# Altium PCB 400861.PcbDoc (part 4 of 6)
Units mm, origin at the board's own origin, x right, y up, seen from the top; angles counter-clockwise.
Board outline 145 x 63.5 mm, 8 copper layers (Top Side, Mid-Layer 1, Mid-Layer 2, Mid-Layer 3, Mid-Layer 4, Mid-Layer 5, Mid-Layer 6, Bottom Side), stack 1.529 mm thick; 284 components, 233 nets, 1158 pads, 3522 vias.
Unrouted connection lines stored in the file: 1.
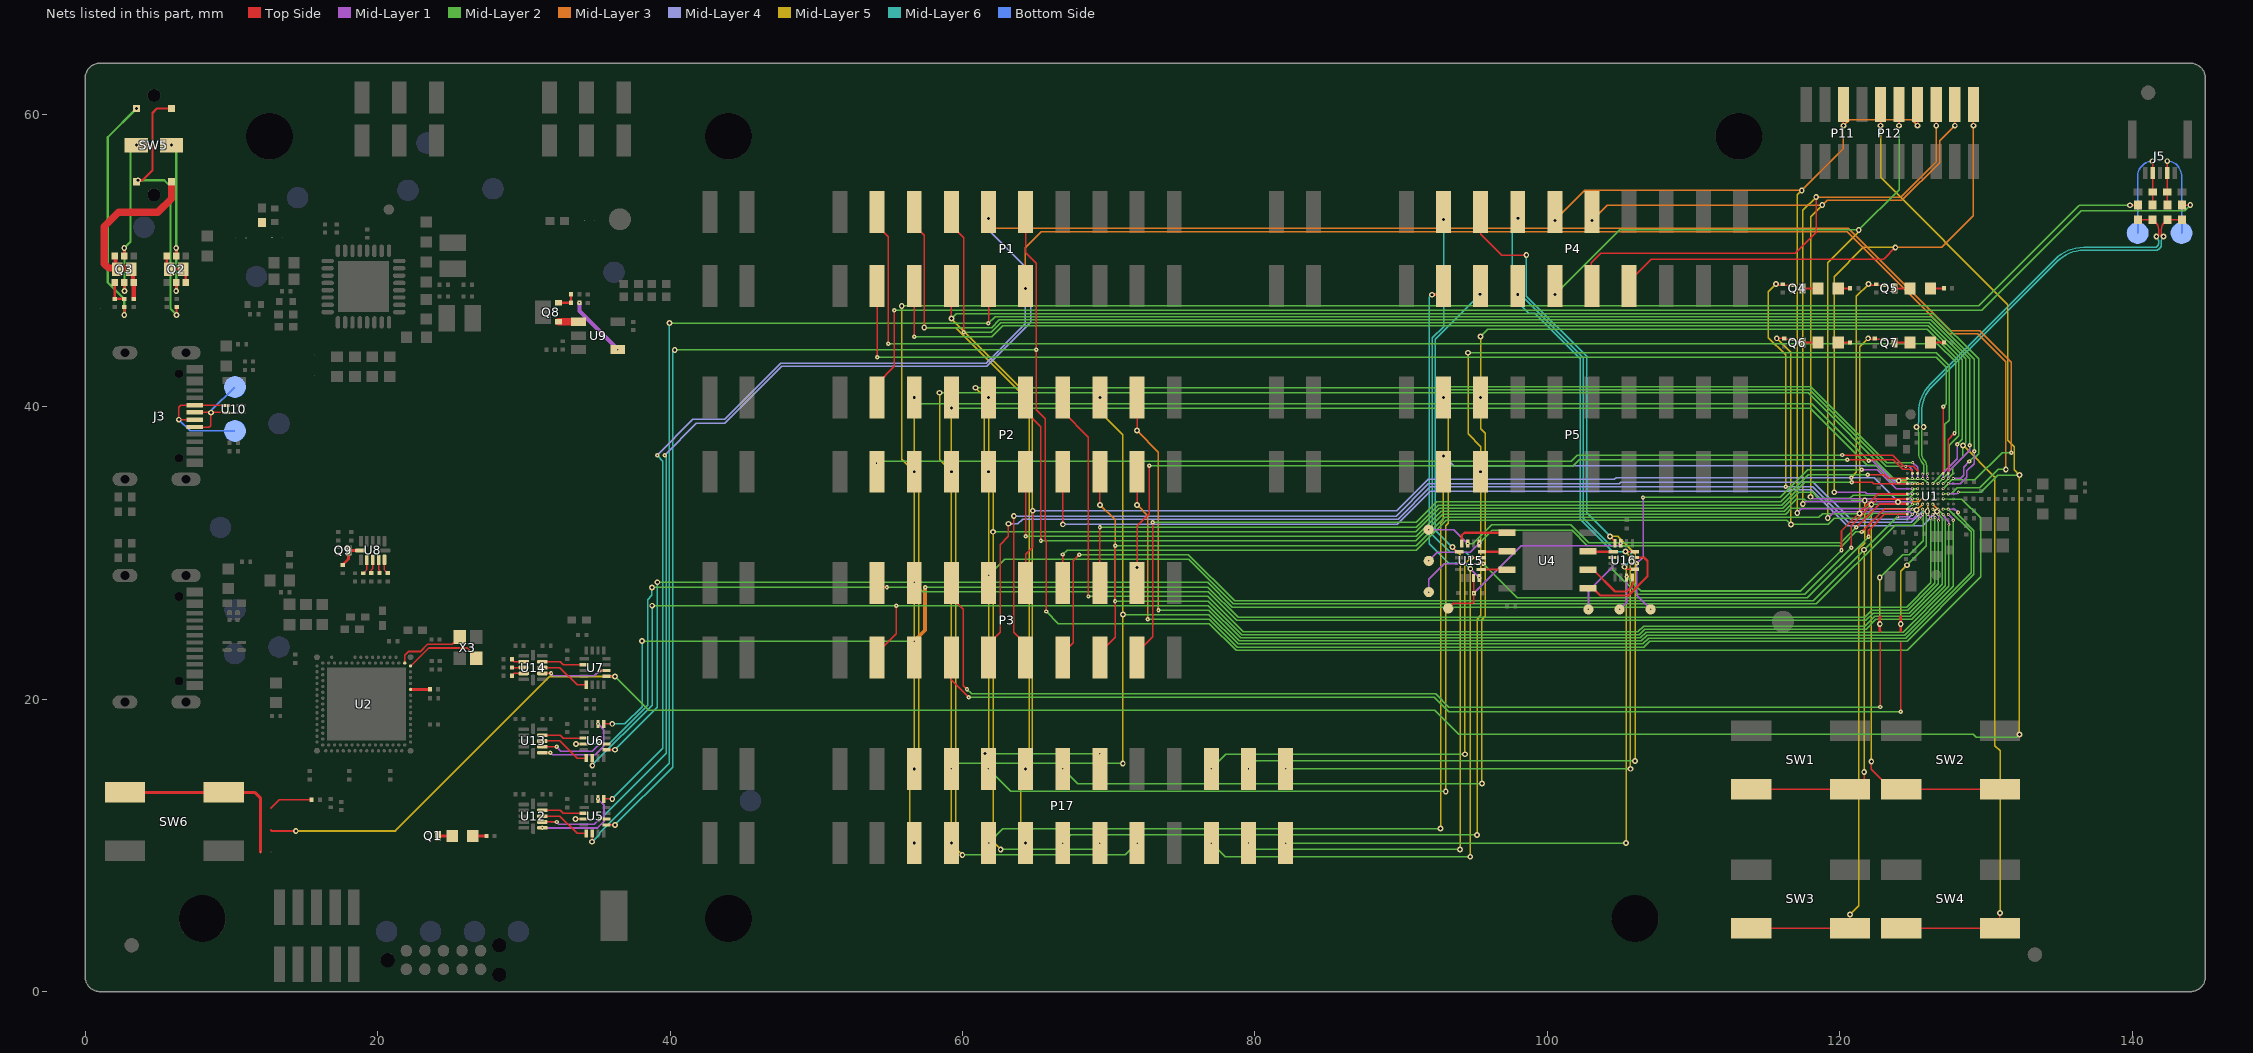
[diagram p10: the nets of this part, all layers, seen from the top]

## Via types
v1: diameter 0.4, hole 0.2, Top Side to Bottom Side, tented both sides, 2426 vias
v2: diameter 0.3, hole 0.1, Top Side to Mid-Layer 1, tented both sides, 299 vias
v3: diameter 0.4, hole 0.2, Mid-Layer 3 to Mid-Layer 4, tented both sides, 197 vias
v4: diameter 0.3, hole 0.1, Mid-Layer 1 to Mid-Layer 2, tented both sides, 197 vias
v5: diameter 0.3, hole 0.1, Mid-Layer 2 to Mid-Layer 3, tented both sides, 91 vias
v6: diameter 0.3, hole 0.1, Mid-Layer 4 to Mid-Layer 5, tented both sides, 81 vias
v7: diameter 0.3, hole 0.1, Mid-Layer 2 to Mid-Layer 3, 71 vias
v8: diameter 0.2, hole 0.1, Top Side to Mid-Layer 1, tented both sides, 64 vias
v9: diameter 0.2, hole 0.1, Mid-Layer 1 to Mid-Layer 2, tented both sides, 41 vias
v10: diameter 0.2, hole 0.1, Mid-Layer 2 to Mid-Layer 3, 19 vias
v11: diameter 0.2, hole 0.1, Mid-Layer 2 to Mid-Layer 3, tented both sides, 14 vias
v12: diameter 0.3, hole 0.1, Mid-Layer 5 to Mid-Layer 6, tented both sides, 12 vias
v13: diameter 0.2, hole 0.1, Mid-Layer 1 to Mid-Layer 2, 4 vias
v14: diameter 0.3, hole 0.1, Top Side to Mid-Layer 1, tented top, 3 vias
v15: diameter 0.2, hole 0.1, Top Side to Mid-Layer 1, tented top, 2 vias
v16: diameter 0.225, hole 0.1, Mid-Layer 1 to Mid-Layer 2, tented both sides, 1 vias

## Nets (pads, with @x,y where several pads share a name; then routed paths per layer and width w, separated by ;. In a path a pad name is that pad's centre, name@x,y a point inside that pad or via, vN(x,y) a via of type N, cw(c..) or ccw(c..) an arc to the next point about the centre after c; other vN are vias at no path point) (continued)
NetLD1_1: LD1.1 Q4.3 | length 1.1
  Top Side w0.15: Q4.3@117.45,48.1 LD1.1@118.502,48.1
NetLD1_2: LD1.2 R25.1 | length 0.8
  Top Side w0.15: LD1.2@119.899,48.1 R25.1@120.715,48.1
NetLD2_1: LD2.1 Q5.3 | length 1.1
  Top Side w0.15: Q5.3@123.75,48.1 LD2.1@124.802,48.1
NetLD2_2: LD2.2 R26.1 | length 0.9
  Top Side w0.15: LD2.2@126.199,48.1 R26.1@127.115,48.1
NetLD3_1: LD3.1 Q6.3 | length 1.1
  Top Side w0.15: Q6.3@117.45,44.4 LD3.1@118.502,44.4
NetLD3_2: LD3.2 R27.1 | length 0.8
  Top Side w0.15: LD3.2@119.899,44.4 R27.1@120.715,44.4
NetLD4_1: LD4.1 Q7.3 | length 1.1
  Top Side w0.15: Q7.3@123.75,44.4 LD4.1@124.802,44.4
NetLD4_2: LD4.2 R28.1 | length 0.9
  Top Side w0.15: LD4.2@126.199,44.4 R28.1@127.115,44.4
NetLD5_1: LD5.1 Q1.3 | length 1
  Top Side w0.203: Q1.3@24.122,10.65 LD5.1@25.102,10.65
NetLD5_2: LD5.2 R5.1 | length 0.9
  Top Side w0.203: LD5.2@26.499,10.65 R5.1@27.433,10.65
NetQ2_2: Q2.2 Q2.5 SW5.5 | length 11.2
  Top Side w0.15: v1(6.22,47.931) Q2.2@6.22,48.506 ; Q2.5@6.22,50.316 v1(6.22,50.862)
  Mid-Layer 2 w0.15: v1(5.9,57.9) 6.22,57.581 v1(6.22,50.862) v1(6.22,47.931)
NetQ2_3: Q2.3 Q2.6 | length 2.9
  Top Side w0.15: Q2.6@5.57,50.316 5.57,49.586 Q2.6@5.745,49.411 Q2.3@6.695,49.411 6.87,49.236 Q2.3@6.87,48.506
NetQ3_1: Q3.1 R22.2 R24.1 SB6.1 | length 1.8
  Top Side w0.15: Q3.1@2.02,48.506 R24.1@2.02,47.391 R22.2@2.675,47.391
NetQ3_2: Q3.2 Q3.5 SW5.2 | length 11.4
  Top Side w0.15: Q3.2@2.67,48.506 2.672,48.503 2.672,47.934 v1(2.675,47.931) ; Q3.5@2.67,50.316 v1(2.67,50.862)
  Mid-Layer 2 w0.15: v1(2.675,47.931) 2.675,50.857 v1(2.67,50.862) 3.1,51.292 3.1,57.5 v1(3.5,57.9)
NetQ3_3: Q3.3 Q3.6 R23.1 SW5.6 | length 14.7
  Top Side w0.3: Q3.6@2.02,50.316 2.072,50.264 2.072,49.534 Q3.6@2.195,49.411 ; Q3.3@3.145,49.411 3.268,49.288 3.268,48.558 Q3.3@3.32,48.506 R23.1@3.32,47.391
  Top Side w0.5: 1.438,49.655 1.3,49.793 ; 1.8,49.5 Q3.6@2.09,49.5 ; Q3.3@3.145,49.411 3.055,49.5 2.195,49.5 Q3.6@2.09,49.5 ; SW5.6@5.9,55.4 5.9,54.234 4.966,53.3 2.269,53.3 1.3,52.331 1.3,49.793 ; 1.3,49.793 1.593,49.5 Q3.6@2.09,49.5
NetQ8_1: Q8.1 U9.1 | length 1.4
  Top Side w0.508: Q8.1@32.368,45.816 U9.1@33.733,45.816
NetQ8_2: Q8.2 R52.1 R54.2 | length 1.4
  Top Side w0.152: Q8.2@32.368,47.116 R54.2@33.229,47.116 R52.1@33.229,47.693
NetQ9_3: Q9.3 R39.1 U8.12 | length 2
  Top Side w0.203: R39.1@17.601,29.189 18.01,29.598 Q9.3@18.01,30.176 U8.12@18.814,30.176
NetR6_2: R6.2 U8.2 | length 1
  Top Side w0.106: R6.2@19.007,28.62 19.264,28.878 U8.2@19.264,29.536
NetR8_1: R8.1 U2.L31 | length 1.3
  Top Side w0.2: U2.L31@22.25,20.675 R8.1@23.565,20.675
NetR12_2: R12.2 U8.3 | length 1
  Top Side w0.106: R12.2@19.567,28.622 19.567,28.841 19.664,28.938 U8.3@19.664,29.536
NetR13_2: R13.2 U8.4 | length 0.9
  Top Side w0.106: U8.4@20.064,29.536 20.064,28.881 20.128,28.817 R13.2@20.128,28.623
NetR16_1: R16.1 SB17.2 SB18.1
NetR21_2: R21.2 SW5.3 SW5.4 | length 18.5
  Top Side w0.15: v1(3.6,55.5) 3.918,55.5 4.6,56.182 4.6,60.1 4.9,60.4 SW5.4@5.9,60.4 ; v1(6.24,46.294) 6.245,46.299 R21.2@6.245,46.821
  Mid-Layer 2 w0.15: v1(3.6,55.5) 5.406,55.5 5.824,55.082 5.824,46.709 v1(6.24,46.294)
NetR22_1: R22.1 SW5.1 | length 15.9
  Top Side w0.15: v1(2.67,46.294) 2.675,46.299 R22.1@2.675,46.821
  Mid-Layer 2 w0.15: v1(2.67,46.294) 2.67,47.37 1.537,48.503 1.537,58.437 v1(3.5,60.4)
NetR35_1: R35.1 SB22.2 | length 3
  Top Side w0.125: SB22.2@12.7,12.55 13.275,13.125 R35.1@15.475,13.125
NetR47_2: R47.2 U8.5 | length 1
  Top Side w0.106: U8.5@20.464,29.536 20.464,28.848 R47.2@20.689,28.623
NetR48_2: R48.2 U14.2 | length 0.9
  Top Side w0.1: R48.2@29.178,22.731 29.342,22.567 U14.2@29.989,22.567
NetR49_2: R49.2 U14.3 | length 0.8
  Top Side w0.1: R49.2@29.178,22.174 29.185,22.167 U14.3@29.989,22.167
NetR50_2: R50.2 U14.4 | length 0.9
  Top Side w0.1: R50.2@29.178,21.617 29.328,21.767 U14.4@29.989,21.767
NetR54_1: R54.1 U9.4 | length 4.3
  Mid-Layer 1 w0.254: v2(33.799,47.116) 33.799,46.547 v2@36.43,43.916
  other v2: 36.433,43.916
NetR56_1: R56.1 SB5.2 TP34.1 U15.15 U16.15 | length 15.1
  Top Side w0.1: TP34.1@93.221,26.216 93.557,26.552 SB5.2@94.981,26.552 v2(94.981,27.262) 94.981,27.559 94.95,27.591 U15.15@94.95,28.308
  Mid-Layer 1 w0.1: v2(94.981,27.262) 98.206,30.487 104.84,30.487 v2(105.023,30.67)
NetSB22_1: SB22.1 SB25.2 SB26.1 SW6.2 | length 13.1
  Top Side w0.2: SW6.2@2.721,13.637 SW6.2@9.471,13.637 11.587,13.637 12,13.224 SB22.1@12,12.55 SB25.2@12,11.05 SB26.1@12,9.55
NetU2_B30: U2.B30 X3.3 | length 4.8
  Top Side w0.125: U2.B30@21.85,22.475 21.85,23.023 22.09,23.263 22.908,23.263 23.408,23.763 25.108,23.763 X3.3@25.6,24.255
NetU2_C31: U2.C31 X3.1 | length 5.3
  Top Side w0.125: U2.C31@22.25,22.275 22.274,22.275 23.512,23.513 26.109,23.513 26.75,22.872 X3.1@26.75,22.805
NetU5_2: U5.2 U12.10 | length 2.9
  Top Side w0.1: U12.10@31.269,12.406 32.488,12.406 32.688,12.206 U5.2@34.095,12.206
NetU5_5: U5.5 U12.9 | length 3.5
  Top Side w0.1: U12.9@31.269,12.006 32.462,12.006 33.637,10.831 U5.5@34.27,10.831
NetU5_10: U5.10 U12.8 | length 5
  Top Side w0.1: U12.8@31.269,11.606 v2(32.238,11.606) ; v2(35.173,11.806) U5.10@35.645,11.806
  Mid-Layer 1 w0.1: 31.857,11.606 v2(32.238,11.606) 32.402,11.442 34.809,11.442 v2(35.173,11.806)
NetU5_14: U5.14 U12.7 | length 6.1
  Top Side w0.125: v2(31.264,11.206) U12.7@31.269,11.206
  Mid-Layer 1 w0.125: v2(31.264,11.206) 35.034,11.206 35.487,11.658 35.487,12.764 v2(35.07,13.181)
NetU6_2: U6.2 U13.10 | length 2.9
  Top Side w0.1: U13.10@31.269,17.546 32.488,17.546 32.688,17.346 U6.2@34.095,17.346
NetU6_5: U6.5 U13.9 | length 3.5
  Top Side w0.1: U13.9@31.269,17.146 32.462,17.146 33.637,15.971 U6.5@34.27,15.971
NetU6_10: U6.10 U13.8 | length 4.7
  Top Side w0.1: U13.8@31.269,16.746 v2(32.238,16.746) ; v2(35.173,16.946) U6.10@35.645,16.946
  Mid-Layer 1 w0.1: v2(32.238,16.746) 32.536,16.449 34.675,16.449 v2(35.173,16.946)
NetU6_14: U6.14 U13.7 | length 6.2
  Top Side w0.1: U13.7@31.269,16.346 v2(31.814,16.346)
  Mid-Layer 1 w0.1: v2(31.814,16.346) 31.961,16.199 34.877,16.199 35.473,16.795 35.473,17.918 v2(35.07,18.322)
NetU7_2: U7.2 U14.10 | length 2.9
  Top Side w0.1: U14.10@31.269,22.567 32.488,22.567 32.688,22.367 U7.2@34.095,22.367
NetU7_5: U7.5 U14.9 | length 3.5
  Top Side w0.1: U14.9@31.269,22.167 32.462,22.167 33.637,20.992 U7.5@34.27,20.992
NetU7_10: U7.10 U14.8 | length 4.6
  Top Side w0.1: U14.8@31.269,21.767 v2(31.857,21.767) ; v2(35.173,21.967) U7.10@35.645,21.967
  Mid-Layer 1 w0.1: v2(31.857,21.767) 32.013,21.612 34.817,21.612 v2(35.173,21.967)
NFC1_N: C56.1 J5.2 R33.2 TP26.1 | length 8.5
  Top Side w0.1: R33.2@142.4,53.8 142.4,54.055 142.4,54.495 C56.1@142.4,54.7 142.4,54.905 J5.2@142.4,56 v1(142.4,56.8)
  Bottom Side w0.1: v1(142.4,56.8) cw(c142.4,55.825) 143.376,55.825 TP26.1@143.376,51.885
NFC2_P: C57.2 J5.4 R34.2 TP28.1 | length 8.5
  Top Side w0.1: R34.2@141.4,53.8 141.4,54.055 141.4,54.495 C57.2@141.4,54.7 141.4,54.905 J5.4@141.4,56 v1(141.4,56.8)
  Bottom Side w0.1: TP28.1@140.376,51.885 140.376,55.776 cw(c141.4,55.776) v1(141.4,56.8)
NFC_N: R3.2 R33.1 U1.J6 | length 29.4
  Top Side w0.1: v1(142.15,51.656) 142.003,51.656 142,51.659 142,52.143 cw(c142.621,52.143) 142.182,52.582 R33.1@142.4,52.8 R3.2@143.4,52.8
  Mid-Layer 1 w0.1: v13(125.985,35.392) 125.985,35.186 ccw(c126.106,35.186) v8(126.02,35.1)
  Mid-Layer 2 w0.1: v5(125.741,38.611) ccw(c126.103,38.248) 125.591,38.248 125.591,36.817 ccw(c126.299,36.817) 125.798,36.316 cw(c125.468,35.985) 125.935,35.985 125.935,35.513 ccw(c126.105,35.513) v13(125.985,35.392)
  Mid-Layer 6 w0.1: v5(125.741,38.611) cw(c126.103,38.973) 125.591,38.973 125.591,39.616 cw(c128.131,39.616) 126.335,41.412 128.973,44.05 128.975,44.05 129.297,44.372 129.297,44.374 134.887,49.964 cw(c136.683,48.168) 136.683,50.708 141.598,50.708 ccw(c141.598,51.055) 141.843,50.809 141.904,50.871 ccw(c141.674,51.102) 142,51.102 142,51.35 cw(c142.375,51.35) 142.11,51.616 v1(142.15,51.656)
  other v3: 125.741,38.611
  other v6: 125.741,38.611
  other v12: 125.741,38.611
NFC_P: R4.2 R34.1 U1.J7 | length 29.3
  Top Side w0.1: R4.2@140.4,52.8 R34.1@141.4,52.8 141.618,52.582 cw(c141.179,52.143) 141.8,52.143 141.8,51.659 141.797,51.656 v1(141.65,51.656)
  Mid-Layer 1 w0.1: v8(125.67,35.1) ccw(c125.635,35.136) 125.685,35.136 v13(125.685,35.4)
  Mid-Layer 2 w0.1: v5(125.241,38.611) cw(c124.878,38.248) 125.391,38.248 125.391,36.817 ccw(c126.299,36.817) 125.657,36.174 cw(c125.468,35.985) 125.735,35.985 125.735,35.521 cw(c125.564,35.521) v13(125.685,35.4)
  Mid-Layer 6 w0.1: v5(125.241,38.611) ccw(c124.878,38.973) 125.391,38.973 125.391,39.616 cw(c128.131,39.616) 126.193,41.553 127.55,42.91 128.89,44.25 128.892,44.25 129.097,44.455 129.097,44.457 134.745,50.105 cw(c136.683,48.168) 136.683,50.908 141.563,50.908 ccw(c141.563,51.139) 141.726,50.976 ccw(c141.548,51.154) 141.8,51.154 141.8,51.35 ccw(c141.425,51.35) 141.69,51.616 v1(141.65,51.656)
  other v3: 125.241,38.611
  other v6: 125.241,38.611
  other v12: 125.241,38.611
nRF54_CON_N: J3.A7 J3.B7 TP22.1 U10.2 | length 9.5
  Top Side w0.099: J3.A7@7.485,39.12 v1(6.4,39.12) 6.4,39.9 cw(c6.62,39.9) 6.62,40.12 7.4,40.12 ccw(c7.427,40.12) 7.427,40.094 U10.2@9.65,40.094 ccw(c9.623,40.094) U10.2@9.623,40.12
  Bottom Side w0.099: v1@6.4,39.2 v1(6.4,39.12) 7.167,38.353 TP22.1@10.236,38.353
nRF54_CON_P: J3.A6 J3.B6 TP23.1 U10.3 | length 6.8
  Top Side w0.099: J3.B6@7.485,38.62 ccw(c7.505,38.62) 7.505,38.6 8.4,38.6 ccw(c8.4,38.8) 8.6,38.8 v1(8.6,39.6) ; J3.A6@7.555,39.55 cw(c7.555,39.62) J3.A6@7.485,39.62 9.623,39.62 cw(c9.623,39.594) U10.3@9.65,39.594
  Bottom Side w0.099: v1(8.6,39.6) 8.6,39.717 TP23.1@10.236,41.353
nRF54_RESET: P11.10 P12.10 SB25.1 U1.F2 U7.9 | length 178.8
  Top Side w0.1: U7.9@35.645,21.567 v1(36.221,21.567) ; v1(122.787,59.228) P12.10@122.787,60.676
  Top Side w0.15: SB25.1@12.7,11.05 12.75,11 v1(14.4,11)
  Mid-Layer 1 w0.1: v8(127.42,34.05) 127.994,34.05 v13(128.11,34.166)
  Mid-Layer 2 w0.1: v1(36.221,21.567) 38.549,19.239 92.304,19.239 93.943,17.6 129.13,17.6 129.327,17.403 132.09,17.403 v5(132.287,17.6) ; v13(128.11,34.166) 129.635,34.166 130.805,35.336 v5(132.289,35.336)
  Mid-Layer 5 w0.1: v1(122.787,59.228) 122.787,55.714 131.503,46.998 131.503,37.71 131.942,37.271 131.942,35.683 v5(132.289,35.336) ; v5(132.287,17.6) v6@132.287,35.335
  Mid-Layer 5 w0.15: v1(14.4,11) 21.2,11 31.767,21.567 v1(36.221,21.567)
  other v3: 132.287,17.6 132.289,35.336
  other v6: 132.287,17.6 132.289,35.336
P0.00: P1.3 U1.K3 | length 85.1
  Top Side w0.1: v2(54.16,43.393) 54.16,43.682 ; 54.16,43.596 54.16,43.682 ; P1.3@54.16,47.67 54.16,43.682 ; U1.K3@127.07,35.45 v4(127.071,40.004)
  Mid-Layer 2 w0.1: v2(54.16,43.393) 126.588,43.393 127.268,42.713 127.268,40.202 v4(127.071,40.004)
  other v2: 127.071,40.004
  other v4: 54.16,43.393
P0.01: P1.4 U1.K2 | length 90.1
  Top Side w0.1: P1.4@54.16,52.75 54.16,52.397 54.912,51.645 v2@54.912,44.321 ; U1.K2@127.42,35.45 127.42,37.756 v4(127.846,38.182)
  Mid-Layer 2 w0.1: v2(54.911,44.321) 126.675,44.321 127.923,43.074 127.923,38.259 v4(127.846,38.182)
  other v2: 127.846,38.182
  other v4: 54.911,44.321
P0.02: P1.5 U1.J3 | length 84.5
  Top Side w0.1: v2(56.7,44.799) P1.5@56.7,47.67
  Mid-Layer 1 w0.1: v8(127.07,35.1) 127.07,35.505 128.025,36.459 128.025,36.832 v4(128.025,37.438)
  Mid-Layer 2 w0.1: v2(56.7,44.799) 61.989,44.799 62.745,45.556 126.047,45.556 128.384,43.219 128.384,37.797 v4(128.025,37.438)
  other v4: 56.7,44.799
P0.03: P1.6 P17.11 U1.J2 | length 129.1
  Top Side w0.1: P1.6@56.7,52.75 56.7,52.414 57.383,51.731 v4(57.383,45.422)
  Mid-Layer 1 w0.1: v8(127.419,35.102) 127.419,35.558 128.884,37.023 v4(128.884,37.379)
  Mid-Layer 2 w0.1: v4(57.383,45.422) 61.992,45.422 62.526,45.956 126.233,45.956 128.884,43.305 v4(128.884,37.379)
  Mid-Layer 5 w0.1: v4(57.383,45.422) 59.551,45.422 64.578,40.395 64.578,15.964 63.999,15.385 63.999,10.481 v6(64.32,10.16)
  other v2: 64.32,10.16 57.383,45.422
  other v3: 64.32,10.16 57.383,45.422
  other v4: 64.32,10.16
  other v5: 64.32,10.16 57.383,45.422
  other v6: 57.383,45.422
P0.04: P1.7 P17.12 U1.J1 | length 115.8
  Top Side w0.1: v4(59.24,46.041) P1.7@59.24,47.67
  Mid-Layer 1 w0.1: v15(127.77,35.1) 128.266,35.1 128.488,35.322 128.488,35.886 v4(128.866,36.264)
  Mid-Layer 2 w0.1: v4(59.24,46.041) 59.583,46.384 126.387,46.384 129.497,43.273 129.497,36.79 129.322,36.614 129.217,36.614 v4(128.866,36.264)
  Mid-Layer 5 w0.1: v4(59.24,46.041) 64.785,40.496 64.785,15.705 v2(64.32,15.24)
  other v2: 59.24,46.041
  other v3: 64.32,15.24 59.24,46.041
  other v4: 64.32,15.24
  other v5: 64.32,15.24 59.24,46.041
  other v6: 64.32,15.24 59.24,46.041
P0.05: P1.8 SW4.2 U1.H3 | length 127.8
  Top Side w0.1: P1.8@59.24,52.75 59.24,52.392 60.081,51.551 v2(60.081,45.114) ; SW4.2@124.209,4.35 SW4.2@130.959,4.35 130.959,5.376 v1(130.961,5.378)
  Mid-Layer 2 w0.1: v2(60.081,45.114) 61.975,45.114 62.617,45.756 126.137,45.756 128.606,43.287 128.606,37.537 v5(128.428,37.359) 128.428,36.567 127.742,35.881 127.742,35.422 v9(127.07,34.75)
  Mid-Layer 5 w0.1: v6@128.444,37.359 130.608,35.195 130.608,16.826 130.961,16.473 v1(130.961,5.378)
  other v3: 128.428,37.359
  other v4: 60.081,45.114
  other v6: 128.428,37.359
  other v8: 127.07,34.75
P0.06: P1.9 U1.H2 U5.6 | length 140.6
  Top Side w0.1: v1(34.67,10.255) U5.6@34.67,10.831 ; v4(61.771,45.723) 61.78,45.733 P1.9@61.78,47.67
  Mid-Layer 1 w0.1: v8(127.42,34.75) 128.256,34.75 128.693,35.187 128.693,35.615 129.197,36.119 v4(129.197,36.964)
  Mid-Layer 2 w0.1: v5(39.949,45.723) 40.841,45.723 v4(61.771,45.723) 62.225,46.178 126.302,46.178 129.209,43.27 129.209,36.976 v4(129.197,36.964)
  Mid-Layer 6 w0.1: v1(34.67,10.255) 35.18,10.765 35.18,10.87 39.949,15.64 v5(39.949,45.723)
  other v2: 61.771,45.723
  other v3: 39.949,45.723
  other v6: 39.949,45.723
  other v12: 39.949,45.723
P0.07: P1.10 U1.G3 U5.3 | length 152.2
  Top Side w0.1: v1(33.519,11.806) U5.3@34.095,11.806
  Mid-Layer 2 w0.095: v9(127.07,34.4) 127.669,34.999
  Mid-Layer 2 w0.1: 127.669,34.999 129.245,34.999 131.105,36.859 131.729,36.859 v5(131.735,36.865)
  Mid-Layer 3 w0.09: v1(61.775,52.875) ccw(c62.45,52.875) 61.85,52.566 ccw(c62.45,52.875) 62.45,52.2
  Mid-Layer 3 w0.1: 62.45,52.2 120.591,52.2 127.591,45.2 129.569,45.2 131.735,43.034 v5(131.735,36.865)
  Mid-Layer 4 w0.1: v12(39.632,36.698) 41.801,38.867 43.746,38.867 47.652,42.773 61.673,42.773 64.681,45.781 64.681,49.206 61.775,52.112 v1(61.775,52.875)
  Mid-Layer 6 w0.1: v1(33.519,11.806) 35.232,11.806 39.745,16.319 39.745,36.584 v12(39.632,36.698)
  other v6: 39.632,36.698
  other v8: 127.07,34.4
P0.08: P1.11 U1.F3 U5.13 | length 143.3
  Top Side w0.1: U5.13@35.47,13.181 v1(36.046,13.181)
  Mid-Layer 2 w0.1: v9(127.07,34.05) 127.625,34.05 128.026,34.451 129.562,34.451 130.827,35.716 v1(131.357,35.716)
  Mid-Layer 3 w0.1: v1(64.3,48.1) 64.3,50.879 65.393,51.972 120.522,51.972 127.495,44.998 129.446,44.998 131.357,43.088 v1(131.357,35.716)
  Mid-Layer 4 w0.1: v12(39.11,36.688) 41.56,39.138 43.728,39.138 47.582,42.993 61.609,42.993 64.3,45.684 v1(64.3,48.1)
  Mid-Layer 6 w0.1: v1(36.046,13.181) 39.511,16.646 39.511,36.287 v12(39.11,36.688)
  other v6: 39.11,36.688
  other v8: 127.07,34.05
P0.09: P1.12 U1.E3 U5.9 | length 161
  Top Side w0.1: U5.9@35.645,11.406 v1(36.221,11.406) ; P1.12@64.32,52.75 64.32,50.547 65.043,49.824 v2(65.043,43.898) 65.043,39.807 65.662,39.188 65.662,30.913 65.722,30.854 v4(65.722,26.003)
  Mid-Layer 2 w0.1: v5(40.316,43.898) 41.423,43.898 v2(65.043,43.898) ; v4(65.722,26.003) 66.554,25.172 76.89,25.172 78.706,23.356 124.617,23.356 129.627,28.366 129.627,32.427 128.359,33.695 127.468,33.695 v8(127.07,33.7)
  Mid-Layer 6 w0.1: v1(36.221,11.406) 40.179,15.364 40.179,43.761 v5(40.316,43.898)
  other v2: 65.722,26.003
  other v3: 40.316,43.898
  other v4: 65.043,43.898
  other v6: 40.316,43.898
  other v9: 127.07,33.7
  other v12: 40.316,43.898
P1.00: P2.3 U1.K8 | length 72.1
  Top Side w0.1: v2(120.167,36.705) 123.612,36.705 124.386,35.93 125.011,35.93 125.32,35.621 U1.K8@125.32,35.45
  Mid-Layer 2 w0.1: v4(54.117,36.156) 54.25,36.29 101.643,36.29 102.059,36.705 v2(120.167,36.705)
  other v2: 54.117,36.156
  other v4: 120.167,36.705
P1.01: P2.4 R3.1 | length 99.2
  Top Side w0.1: P2.4@54.16,40.05 54.16,41.584 55.343,42.767 v2(55.343,46.6) ; R3.1@143.4,53.8 143.404,53.805 v1(143.97,53.805)
  Mid-Layer 2 w0.1: v2(55.343,46.6) 129.7,46.6 136.516,53.416 143.581,53.416 v1(143.97,53.805)
  other v4: 55.343,46.6
P1.02: P2.5 P17.5 R4.1 | length 124.8
  Top Side w0.1: v1(139.841,53.786) 140.386,53.786 R4.1@140.4,53.8
  Mid-Layer 2 w0.1: v5(55.842,46.902) 129.502,46.902 136.357,53.757 cw(c136.427,53.686) 136.427,53.786 v1(139.841,53.786)
  Mid-Layer 5 w0.1: v5(55.842,46.902) 55.842,36.418 v6(56.7,35.56) 56.7,15.674 56.397,15.371 56.397,10.463 v6(56.7,10.16)
  other v2: 56.7,10.16 56.7,35.56
  other v3: 56.7,10.16 56.7,35.56 55.842,46.902
  other v4: 56.7,10.16 56.7,35.56
  other v5: 56.7,10.16 56.7,35.56
  other v6: 55.842,46.902
P1.03: P2.6 P17.6 U1.H9 | length 96.4
  Mid-Layer 1 w0.1: v4(121.995,36.314) 122.252,36.314 123.816,34.75 v8(124.97,34.75)
  Mid-Layer 2 w0.1: v4(56.7,40.64) 57.115,40.225 118.084,40.225 v4(121.995,36.314)
  Mid-Layer 5 w0.1: v6@56.69,40.64 56.69,36.548 57,36.238 57,15.54 v6(56.7,15.24)
  other v2: 56.7,15.24 56.7,40.64
  other v3: 56.7,15.24 56.7,40.64
  other v4: 56.7,15.24
  other v5: 56.7,15.24 56.7,40.64
  other v6: 56.7,40.64
P1.04: P2.7 P17.7 U1.J9 | length 100.6
  Mid-Layer 1 w0.1: v9(124.513,35.925) 124.744,35.925 124.97,35.699 v8(124.97,35.1)
  Mid-Layer 2 w0.1: v5(58.431,40.964) 92.387,40.963 92.582,41.159 117.944,41.159 123.177,35.925 v9(124.513,35.925)
  Mid-Layer 5 w0.1: v5(58.431,40.964) 58.431,36.369 v6(59.24,35.56) v6(59.24,10.16)
  other v2: 59.24,10.16 59.24,35.56
  other v3: 59.24,10.16 59.24,35.56 58.431,40.964
  other v4: 59.24,10.16 59.24,35.56
  other v5: 59.24,10.16 59.24,35.56
  other v6: 58.431,40.964
P1.05: P2.8 P17.17 U1.H8 | length 111.4
  Mid-Layer 1 w0.1: v8@125.297,34.727 v9(125.32,34.75)
  Mid-Layer 2 w0.1: v4(59.24,39.914) 117.968,39.914 121.879,36.003 122.454,36.003 123.606,34.851 125.212,34.851 125.313,34.75 v9(125.32,34.75) ; v6(59.985,9.354) 71.134,9.354 v4(71.94,10.16)
  Mid-Layer 5 w0.1: v4(59.24,39.914) 59.24,36.023 59.541,35.722 59.541,9.799 v6(59.985,9.354)
  other v2: 71.94,10.16 59.24,39.914
  other v3: 59.985,9.354 59.24,39.914
  other v5: 59.985,9.354 59.24,39.914
  other v6: 59.24,39.914
  other v8: 125.32,34.75
P1.06: P2.9 P17.16 U1.J8 | length 100.8
  Mid-Layer 1 w0.1: v9(124.991,36.181) 125.32,35.852 v8(125.32,35.1)
  Mid-Layer 2 w0.1: v5(60.888,41.304) 92.4,41.304 92.466,41.37 118.024,41.37 123.213,36.181 v9(124.991,36.181) ; v6(61.542,16.278) v4(69.391,16.278)
  Mid-Layer 5 w0.1: v5(60.888,41.304) 61.475,40.717 61.475,35.865 v6(61.78,35.56) 61.78,16.516 v6(61.542,16.278)
  other v2: 69.391,16.278 61.78,35.56
  other v3: 61.542,16.278 61.78,35.56 60.888,41.304
  other v4: 61.78,35.56
  other v5: 61.542,16.278 61.78,35.56
  other v6: 60.888,41.304
P1.07: P2.10 P17.15 U1.G8 | length 103
  Mid-Layer 2 w0.1: v5(62.09,31.454) 91,31.454 92.607,33.06 116.115,33.06 117.202,34.147 118.146,34.147 118.539,33.754 120.696,33.754 120.909,33.967 124.698,33.967 125.131,34.4 v8(125.32,34.4) ; v6(62.612,9.726) 68.966,9.726 v4(69.4,10.16)
  Mid-Layer 5 w0.1: v6(61.78,40.64) 61.78,36.148 62.097,35.832 62.097,31.46 v5(62.09,31.454) 62.09,10.248 v6(62.612,9.726)
  other v2: 69.4,10.16 61.78,40.64
  other v3: 62.612,9.726 62.09,31.454 61.78,40.64
  other v4: 61.78,40.64
  other v5: 62.612,9.726 61.78,40.64
  other v6: 62.09,31.454
  other v9: 125.32,34.4
P1.08: P2.11 SW3.2 U1.F8 | length 102.6
  Top Side w0.1: v2(64.32,31.148) P2.11@64.32,34.97 ; SW3.2@113.948,4.35 SW3.2@120.698,4.35 v1(120.698,5.273)
  Mid-Layer 2 w0.1: v2(64.32,31.148) 91.037,31.148 92.745,32.856 116.209,32.856 117.04,33.687 117.566,33.687 117.71,33.543 120.796,33.543 120.854,33.6 v6(121.706,33.6) 121.806,33.7 124.715,33.7 125.065,34.05 v9(125.32,34.05)
  Mid-Layer 5 w0.1: v1(120.698,5.273) 121.306,5.881 121.306,30.287 121.706,30.687 v6(121.706,33.6)
  other v3: 121.706,33.6
  other v4: 64.32,31.148
  other v5: 121.706,33.6
  other v8: 125.32,34.05
P1.09: P2.12 SW2.2 U1.E8 | length 98.3
  Top Side w0.1: P2.12@64.32,40.05 64.32,39.684 65.366,38.638 v2(65.366,30.836) ; v1(122.158,15.743) 122.158,15.229 123.587,13.8 SW2.2@124.3,13.8 ; SW2.2@124.3,13.85 SW2.2@130.959,13.85
  Mid-Layer 2 w0.1: v2(65.366,30.836) 91.012,30.836 92.83,32.655 116.298,32.655 116.696,33.052 121.882,33.052 v6(122.158,33.329) 122.159,33.327 124.632,33.327 125.005,33.7 v9(125.32,33.7)
  Mid-Layer 5 w0.1: v1(122.158,15.743) v6(122.158,33.329)
  other v3: 122.158,33.329
  other v4: 65.366,30.836
  other v5: 122.158,33.329
  other v8: 125.32,33.7
P1.10: P2.13 U1.D5 | length 65.8
  Top Side w0.1: v3(66.86,31.967) P2.13@66.86,34.97
  Mid-Layer 3 w0.1: v8(126.37,33.35) 126.648,33.073 v3(126.648,32.852)
  Mid-Layer 4 w0.1: v3(66.86,31.967) 89.727,31.967 91.987,34.227 116.502,34.227 116.607,34.332 118.047,34.332 120.499,31.881 125.676,31.881 v3(126.648,32.852)
  other v2: 66.86,31.967
  other v4: 66.86,31.967
  other v5: 66.86,31.967
  other v9: 126.37,33.35
  other v11: 126.37,33.35
P1.11: P2.14 U1.C5 | length 79.8
  Top Side w0.1: P2.14@66.86,40.05 66.86,39.689 68.616,37.933 v4(68.616,27.03)
  Mid-Layer 2 w0.1: v4@68.667,27.03 76.779,27.03 79.195,24.614 106.197,24.614 106.584,25.001 121.71,25.001 122.38,25.671 124.815,25.671 127.002,27.859 127.002,32.365 126.37,32.997 v9(126.37,33)
  other v2: 68.616,27.03
  other v8: 126.37,33
P1.12: P2.15 U1.C4 | length 73.2
  Top Side w0.1: v1(69.4,33.294) P2.15@69.4,34.97
  Mid-Layer 2 w0.1: v5(70.433,26.702) 76.82,26.702 79.111,24.41 106.281,24.41 106.671,24.801 121.802,24.801 122.47,25.47 124.91,25.47 127.202,27.761 127.202,32.48 126.72,32.962 v8(126.72,33)
  Mid-Layer 3 w0.1: v1(69.4,33.294) 70.433,32.261 v5(70.433,26.702)
  other v9: 126.72,33
P1.13: P2.16 P17.8 U1.C3 | length 103.8
  Mid-Layer 1 w0.1: v8(127.07,33) 127.073,33 v9@127.074,33.001
  Mid-Layer 2 w0.1: v2(59.24,15.24) 59.608,15.608 v6(70.964,15.608) ; v5(70.966,25.792) 76.856,25.792 78.862,23.786 106.527,23.786 106.931,24.19 124.52,24.19 128.979,28.649 128.979,31.459 127.436,33.001 127.071,33.001 v8(127.07,33)
  Mid-Layer 5 w0.1: v6(69.4,40.64) 69.4,39.665 70.966,38.099 v5(70.966,25.792) 70.966,15.611 v6(70.964,15.608)
  other v2: 69.4,40.64
  other v3: 70.964,15.608 70.966,25.792 69.4,40.64
  other v4: 59.24,15.24 69.4,40.64
  other v5: 70.964,15.608 69.4,40.64
  other v6: 70.966,25.792
  other v9: 127.07,33
P1.14: P2.17 U1.C2 | length 74.6
  Top Side w0.1: v1(71.94,33.294) P2.17@71.94,34.97
  Mid-Layer 1 w0.1: v8(127.42,33) 127.865,33 v4(128.089,32.776)
  Mid-Layer 2 w0.1: v5(72.671,25.485) 76.874,25.485 78.79,23.568 106.593,23.568 107.01,23.985 124.63,23.985 129.18,28.535 129.18,31.54 128.094,32.627 128.094,32.772 v4(128.089,32.776)
  Mid-Layer 3 w0.1: v1(71.94,33.294) 72.671,32.563 v5(72.671,25.485)
P1.15: P2.18 U1.B2 | length 76.4
  Top Side w0.1: v1(71.94,38.374) P2.18@71.94,40.05
  Mid-Layer 1 w0.1: v8(127.42,32.65) 127.758,32.313 v16(127.758,32.238)
  Mid-Layer 2 w0.1: v5(73.403,26.095) 76.838,26.095 78.94,23.993 106.439,23.993 106.841,24.395 124.428,24.395 127.763,27.73 127.763,32.233 v16(127.758,32.238)
  Mid-Layer 3 w0.1: v1(71.94,38.374) 73.403,36.911 v5(73.403,26.095)
P1.16: P3.3 U1.B3 U6.6 | length 113.9
  Top Side w0.1: U6.6@34.67,15.971 34.67,15.486 v1(34.679,15.477) ; P3.3@54.16,22.27 54.16,23.19 55.46,24.49 v2(55.46,26.384)
  Mid-Layer 1 w0.1: v8(127.07,32.65) 127.07,32.536 127.461,32.145 v9(127.461,31.949)
  Mid-Layer 2 w0.1: v5(38.776,26.401) v4@55.443,26.401 ; v2(55.46,26.384) v4@55.443,26.401 ; v9(127.461,31.949) 127.461,27.728 124.333,24.599 106.753,24.599 106.352,24.199 79.024,24.199 76.822,26.401 v4@55.443,26.401
  Mid-Layer 6 w0.1: v1(34.679,15.477) 34.679,15.507 38.776,19.604 v5(38.776,26.401)
  other v3: 38.776,26.401
  other v4: 55.46,26.384
  other v6: 38.776,26.401
  other v12: 38.776,26.401
P1.17: P3.4 U1.B4 U6.3 | length 110.4
  Top Side w0.1: v1(33.571,16.946) U6.3@34.095,16.946 ; P3.4@54.16,27.35 54.465,27.654 v2(54.832,27.654)
  Mid-Layer 1 w0.1: v8(126.72,32.65) 126.72,32.581 126.777,32.524 126.777,32.317 126.72,32.26 126.72,32.254 v9(126.752,32.222) v9@126.752,32.291
  Mid-Layer 2 w0.1: v5(38.757,27.654) v2(54.832,27.654) 56.975,27.654 57.285,27.344 76.798,27.344 78.753,25.389 121.788,25.389 122.283,25.884 124.736,25.884 126.752,27.901 v9(126.752,32.222)
  Mid-Layer 6 w0.1: v1(33.571,16.946) 35.826,16.946 38.462,19.583 38.462,26.81 38.757,27.105 v5(38.757,27.654)
  other v3: 38.757,27.654
  other v4: 54.832,27.654
  other v6: 38.757,27.654
  other v12: 38.757,27.654
P1.18: P3.5 U1.B5 U6.13 | length 105.9
  Top Side w0.1: U6.13@35.47,18.322 v1(36.046,18.322)
  Mid-Layer 1 w0.1: v8(126.37,32.65) 126.532,32.424 v9@126.528,32.421
  Mid-Layer 2 w0.1: v5(38.082,23.976) v5(56.7,23.976) ; v5(57.44,27.664) 76.789,27.664 78.855,25.598 121.705,25.598 122.202,26.095 124.645,26.095 126.482,27.932 126.482,32.312 cw(c126.635,32.312) v9(126.527,32.421) v9@126.508,32.402
  Mid-Layer 3 w0.254: v5(56.7,23.976) 57.44,24.716 v5(57.44,27.664)
  Mid-Layer 6 w0.1: v1(36.046,18.322) 36.901,18.322 38.082,19.503 v5(38.082,23.976)
  other v2: 56.7,23.976
  other v3: 38.082,23.976
  other v4: 56.7,23.976
  other v6: 38.082,23.976
  other v12: 38.082,23.976
P1.19: P3.6 U1.B6 U6.9 | length 106.5
  Top Side w0.1: U6.9@35.645,16.546 v1(36.221,16.546)
  Mid-Layer 1 w0.1: v8(126.02,32.65) 126.02,32.647 126.211,32.456 126.211,32.392 v9(126.225,32.379)
  Mid-Layer 2 w0.1: v5(39.126,28.004) v2(56.7,28.004) 76.759,28.004 78.455,26.308 124.573,26.308 126.225,27.96 v9(126.225,32.379)
  Mid-Layer 6 w0.1: v1(36.221,16.546) 39.126,19.452 v5(39.126,28.004)
  other v3: 39.126,28.004
  other v4: 56.7,28.004
  other v6: 39.126,28.004
  other v12: 39.126,28.004
P1.20: P3.7 SB3.2 | length 71.6
  Top Side w0.1: P3.7@59.24,22.27 59.24,21.325 v4(60.437,20.128) ; v2@124.172,19.175 SB3.2@124.172,23.95
  Mid-Layer 2 w0.1: v4(60.437,20.128) 92.276,20.128 93.255,19.149 v4@124.171,19.149 ; v4@124.171,19.174 v4@124.172,19.175
  other v2: 124.172,19.15 60.437,20.128
  other v4: 124.172,19.15
P1.20/XL1: SB1.1 SB3.1 U1.C6 | length 9.7
  Top Side w0.15: 124.138,25.616 SB1.1@124.172,25.65
  Top Side w0.152: SB3.1@124.172,24.65 v2(124.172,25.15) SB1.1@124.172,25.65
  Mid-Layer 2 w0.1: v6(124.596,29.171) 125.914,30.489 125.914,32.867 126.02,32.973 v9(126.02,33)
  Mid-Layer 5 w0.1: v2(124.172,25.15) 124.172,28.747 v6(124.596,29.171)
  other v3: 124.172,25.15 124.596,29.171
  other v4: 124.172,25.15
  other v5: 124.172,25.15 124.596,29.171
  other v6: 124.172,25.15
  other v8: 126.02,33
P1.21: P3.8 SB4.2 | length 74.6
  Top Side w0.1: P3.8@59.24,27.35 59.24,26.979 60.067,26.152 60.067,20.931 v2(60.307,20.691) ; P3.8@59.24,27.94 P3.8@59.263,27.917 ; v2(122.771,19.471) 122.772,19.473 SB4.2@122.772,23.95
  Mid-Layer 2 w0.1: v2(60.307,20.691) 60.622,20.376 92.358,20.376 93.262,19.471 v2(122.771,19.471)
  other v4: 122.771,19.471 60.307,20.691
P1.21/XL2: SB2.1 SB4.1 U1.C7 | length 10.4
  Top Side w0.15: SB4.1@122.772,24.65 122.738,24.685 v6(122.738,25.139) 122.738,25.616 SB2.1@122.772,25.65
  Mid-Layer 2 w0.1: v5(122.737,28.32) 124.316,29.899 124.76,29.899 125.713,30.851 125.713,32.898 ccw(c125.568,32.898) v9(125.67,33) v9@125.67,32.998
  Mid-Layer 5 w0.1: v6(122.738,25.139) v5(122.737,28.32)
  other v2: 122.738,25.139
  other v3: 122.738,25.139 122.737,28.32
  other v4: 122.738,25.139
  other v5: 122.738,25.139
  other v6: 122.737,28.32
  other v8: 125.67,33
P1.22: P3.9 Q4.1 R32.1 U1.D6 | length 91.7
  Top Side w0.1: P3.9@61.78,22.27 P3.9@61.78,22.86 61.78,23.781 62.573,24.573 62.573,30.575 63.143,31.145 v2(63.143,32.003) ; v1(115.635,48.392) ccw(c115.795,48.552) 115.795,48.325 Q4.1@116.75,48.325
  Mid-Layer 3 w0.1: v3(125.984,32.831) 126.02,32.868 v9(126.02,33.35)
  Mid-Layer 4 w0.1: v2(63.143,32.003) 63.794,32.003 64.114,32.322 89.793,32.322 92.002,34.532 v6(116.295,34.532) 118.152,34.532 120.589,32.096 124.902,32.096 125.637,32.831 v3(125.984,32.831)
  Mid-Layer 5 w0.1: v1(115.635,48.392) 115.103,47.861 115.103,44.738 116.295,43.546 v6(116.295,34.532)
  other v3: 63.143,32.003
  other v4: 63.143,32.003
  other v5: 63.143,32.003
  other v8: 126.02,33.35
  other v11: 126.02,33.35
P1.23: P3.10 U1.B7 | length 68.2
  Mid-Layer 1 w0.1: v9(125.463,32.386) 125.67,32.594 v8(125.67,32.65)
  Mid-Layer 2 w0.1: v4(61.78,28.489) 62.876,29.585 75.462,29.585 78.531,26.516 118.404,26.516 123.805,31.918 124.994,31.918 v9(125.463,32.386)
  other v2: 61.78,28.489
P1.24: P3.11 U1.D7 | length 75.2
  Top Side w0.1: v1(63.51,32.533) 63.51,24.59 64.32,23.78 P3.11@64.32,22.86 P3.11@64.32,22.27
  Mid-Layer 3 w0.1: v3(125.257,32.954) 125.274,32.954 v8(125.67,33.35)
  Mid-Layer 4 w0.1: v1(63.51,32.533) 89.653,32.533 91.869,34.749 104.915,34.749 105.008,34.842 118.198,34.842 120.737,32.303 124.606,32.303 v3(125.257,32.954)
  other v9: 125.67,33.35
  other v11: 125.67,33.35
P1.25: P3.12 Q5.1 R29.1 U1.E7 | length 83.1
  Top Side w0.1: P3.12@64.32,27.35 64.32,29.922 64.806,30.407 v2@64.806,32.888 ; v1(121.967,48.392) ccw(c122.127,48.552) 122.127,48.325 Q5.1@123.05,48.325
  Mid-Layer 3 w0.1: v3(123.991,33.504) 125.408,33.504 125.604,33.7 v8(125.67,33.7)
  Mid-Layer 4 w0.1: v3(64.803,32.892) 89.699,32.892 91.843,35.035 104.583,35.035 104.7,35.152 v6(120.78,35.152) 122.343,35.152 v3(123.991,33.504)
  Mid-Layer 5 w0.1: v6(120.78,35.152) 121.143,35.514 121.143,47.568 v1(121.967,48.392)
  other v2: 64.803,32.892
  other v4: 64.803,32.892
  other v5: 64.803,32.892
  other v9: 125.67,33.7
  other v11: 125.67,33.7
P1.26: P3.13 SW1.2 U1.B8 | length 93.4
  Top Side w0.1: P3.13@66.86,22.27 66.86,23.177 67.561,23.878 67.561,29.475 v2(67.975,29.889) ; SW1.2@113.948,13.85 SW1.2@120.698,13.85 121.608,13.85 121.672,13.914 v1(121.672,15.027)
  Mid-Layer 1 w0.1: v9(123.974,32.476) 124.634,32.476 124.767,32.343 125.017,32.343 125.32,32.647 v8(125.32,32.65)
  Mid-Layer 2 w0.1: v2(67.975,29.889) 75.449,29.889 78.609,26.73 118.174,26.73 v5(121.669,30.224) ; v5@121.672,30.227 v5(121.669,30.224) ; v9(123.974,32.476) 123.921,32.476 v5(121.669,30.224)
  Mid-Layer 5 w0.1: v1(121.672,15.027) v6@121.672,30.227
  other v3: 121.669,30.224
  other v4: 67.975,29.889
  other v6: 121.669,30.224
P1.27: P3.14 Q6.1 R30.1 U1.C8 | length 76.7
  Top Side w0.1: P3.14@66.86,27.35 v2(66.86,29.905) ; v1(115.689,44.688) 115.692,44.685 R30.1@116.2,44.685 ccw(c116.345,44.83) 116.345,44.625 Q6.1@116.75,44.625
  Mid-Layer 2 w0.1: v2(66.86,29.905) 67.148,30.193 91.028,30.193 93.07,32.235 116.383,32.235 v6(116.658,31.96) 119.209,31.96 119.631,32.382 121.924,32.382 122.276,32.734 124.618,32.734 124.883,33 v9(125.32,33)
  Mid-Layer 5 w0.1: v1(115.689,44.688) 116.659,43.718 v6(116.658,31.96) v6(116.658,31.96)
  other v3: 116.658,31.96
  other v4: 66.86,29.905
  other v5: 116.658,31.96
  other v8: 125.32,33
P1.28: P3.15 Q7.1 R31.1 U1.D8 | length 78.1
  Top Side w0.1: P3.15@69.4,22.27 69.4,23.172 70.458,24.23 v2(70.458,30.495) ; v1(121.943,44.688) ccw(c122.096,44.841) 122.096,44.625 Q7.1@123.05,44.625
  Mid-Layer 2 w0.1: v2(70.458,30.495) 91.037,30.495 92.986,32.444 118.565,32.444 118.824,32.703 v6(121.352,32.703) 121.902,32.703 122.223,33.023 124.621,33.023 124.948,33.35 v9(125.32,33.35)
  Mid-Layer 5 w0.1: v6(121.352,32.703) 121.352,44.097 v1(121.943,44.688)
  other v3: 121.352,32.703
  other v4: 70.458,30.495
  other v5: 121.352,32.703
  other v8: 125.32,33.35
P1.29: P3.16 U1.H10 | length 60.9
  Top Side w0.1: P3.16@69.4,27.35 69.4,31.749 v2@69.402,31.751 ; v2(120.811,34.842) 122.222,34.842 122.314,34.75 ; 122.314,34.751 U1.H10@124.62,34.75
  Mid-Layer 2 w0.1: v2(69.402,31.776) 91.036,31.776 92.538,33.279 116.045,33.279 117.609,34.842 v2(120.811,34.842)
  other v4: 69.402,31.776 120.811,34.842
P1.30: P3.17 U1.J10 | length 63.3
  Top Side w0.1: P3.17@71.94,22.27 71.94,23.199 73.023,24.282 v2(73.023,32.096) ; v2(121.926,35.368) 123.049,35.368 123.317,35.1 U1.J10@124.62,35.1
  Mid-Layer 2 w0.1: v2(73.023,32.096) 91.025,32.096 92.424,33.495 105.003,33.495 115.971,33.495 117.844,35.368 v2(121.926,35.368)
  other v4: 73.023,32.096 121.926,35.368
P1.31: P3.18 U1.K9 | length 61.8
  Top Side w0.1: P3.18@71.94,27.35 71.94,31.851 72.778,32.689 v2(72.778,35.971) ; v2(120.51,36.387) 123.643,36.387 124.313,35.717 124.832,35.717 124.97,35.579 U1.K9@124.97,35.45
  Mid-Layer 2 w0.1: v2(72.778,35.971) 101.775,35.971 102.191,36.387 v2(120.51,36.387)
  other v1: 71.94,29.025
  other v4: 72.778,35.971 120.51,36.387
P2.00: TP13.1 U1.B10 U15.2 | length 37.7
  Top Side w0.127: v4(121.968,31.12) 121.968,31.571 123.047,32.65 U1.B10@124.62,32.65
  Mid-Layer 1 w0.1: v2(91.892,27.335) 91.892,28.215 92.958,29.281 v4(95.601,29.281)
  Mid-Layer 2 w0.1: v4(95.601,29.281) 97.95,26.932 117.78,26.932 v4(121.968,31.12)
  other v2: 95.601,29.281 121.968,31.12
P2.00_A: P4.3 P17.21 U15.16 | length 60.1
  Top Side w0.1: P17.21@77.02,10.16 v2(77.02,10.162)
  Top Side w0.2: v1(92.111,47.668) 92.112,47.67 P4.3@92.895,47.67
  Mid-Layer 1 w0.1: v1(94.73,28.925) v4(95.35,28.306)
  Mid-Layer 2 w0.1: v2(77.02,10.162) 77.954,9.228 v6(94.729,9.228)
  Mid-Layer 5 w0.1: v6(94.729,9.228) 94.73,9.23 v1(94.73,28.925)
  Mid-Layer 6 w0.1: v1(92.111,47.668) 91.928,47.486 91.928,30.636 93.261,29.304 93.894,29.304 93.942,29.351 94.304,29.351 v1(94.73,28.925)
  other v2: 95.35,28.306
  other v3: 94.729,9.228
  other v4: 77.02,10.162
  other v5: 94.729,9.228
P2.00_B: U4.7 U15.1 | length 1.8
  Top Side w0.1: U4.7@97.203,28.883 U4.7@97.234,28.853
  Top Side w0.152: U15.1@95.475,28.883 U4.7@97.203,28.883
P2.01: TP29.1 U1.C10 U15.5 | length 35.1
  Top Side w0.127: v4(121.493,31.444) 123.05,33 U1.C10@124.62,33
  Mid-Layer 1 w0.1: v2(91.892,29.464) 92.47,30.042 94.737,30.042 v4(95.353,30.658)
  Mid-Layer 2 w0.1: v4(95.353,30.658) 96.247,31.553 101.695,31.553 102.746,30.502 120.159,30.502 121.101,31.444 v4(121.493,31.444)
  other v2: 95.353,30.658 121.493,31.444
P2.01_A: P4.4 P17.22 U15.3 | length 57.3
  Top Side w0.1: v2(77.018,15.24) v2(77.018,15.24) ; v1(94.788,29.683) U15.3@95.525,29.683
  Mid-Layer 2 w0.1: v2(77.018,15.24) 78.015,16.237 94.358,16.237 v5(94.361,16.239)
  Mid-Layer 5 w0.1: v5(94.361,16.239) 94.361,29.256 v1(94.788,29.683)
  Mid-Layer 6 w0.1: v1(92.9,52.8) 92.9,45.483 92.134,44.717 92.134,31.262 93.354,30.042 94.429,30.042 v1(94.788,29.683)
  other v3: 94.361,16.239
  other v4: 77.018,15.24
  other v6: 94.361,16.239
P2.01_B: U4.6 U15.4 | length 1.7
  Top Side w0.152: U15.4@95.525,30.083 97.194,30.083 U4.6@97.234,30.123
P2.02: TP30.1 U1.D10 U15.7 | length 35.3
  Top Side w0.127: v2(121.12,31.756) 122.714,33.35 U1.D10@124.62,33.35
  Mid-Layer 1 w0.1: v2(91.876,31.593) 93.61,31.593 v4(94.55,30.653)
  Mid-Layer 2 w0.1: v4(94.55,30.653) 94.902,30.653 96.201,31.952 101.598,31.952 102.845,30.705 120.069,30.705 v2(121.12,31.756)
  other v2: 94.55,30.653
  other v4: 121.12,31.756
P2.02_A: P4.5 P17.23 U15.9 | length 55.3
  Top Side w0.1: P17.23@79.56,10.16 v2(79.56,10.17) ; v1(93.513,30.403) 93.833,30.083 U15.9@93.975,30.083
  Mid-Layer 2 w0.1: v2(79.56,10.17) 80.004,9.726 v6(94.035,9.727) v6(94.035,9.727) v5@94.136,9.727
  Mid-Layer 5 w0.1: v1(93.513,30.403) 94.035,29.881 v6(94.035,9.727)
  Mid-Layer 6 w0.1: v1(93.513,30.403) 92.339,31.577 92.339,44.639 v1(95.4,47.7)
  other v3: 94.035,9.727
  other v4: 79.56,10.17
  other v5: 94.035,9.727
P2.02_B: U4.5 U15.8 | length 3.7
  Top Side w0.152: U15.8@94.15,30.658 94.15,31.215 94.328,31.393 U4.5@97.234,31.393
P2.03: TP31.1 U1.E10 U16.2 | length 29.5
  Top Side w0.127: v2(120.785,30.364) 120.785,31.871 122.614,33.7 U1.E10@124.62,33.7
  Mid-Layer 1 w0.127: v2(102.808,26.146) 102.808,27.383 104.448,29.022 v4(104.448,29.695)
  Mid-Layer 2 w0.127: v4(104.448,29.695) 104.448,28.907 106.174,27.181 117.602,27.181 v2(120.785,30.364)
  other v2: 104.448,29.695
  other v4: 120.785,30.364
P2.03_A: P4.6 P17.24 U16.16 | length 69.9
  Top Side w0.1: P4.6@95.435,52.75 95.435,51.815 96.876,50.374 v1(98.56,50.374) ; v1(104.29,31.14) 104.623,30.807 U16.16@104.623,30.67
  Mid-Layer 2 w0.1: v2(79.56,15.24) 80.103,15.783 v5(105.997,15.783)
  Mid-Layer 5 w0.1: v1(104.29,31.14) 104.808,31.14 105.997,29.951 v6@105.997,15.784
  Mid-Layer 6 w0.1: v1(98.56,50.374) 98.56,47.568 102.683,43.445 102.683,32.747 v1(104.29,31.14)
  other v3: 105.997,15.783
  other v4: 79.56,15.24
  other v6: 105.997,15.783
P2.03_B: U4.3 U16.1 | length 1.7
  Top Side w0.152: U4.3@102.774,30.123 102.801,30.095 U16.1@104.498,30.095
P2.04: TP32.1 U1.F10 U16.7 | length 25.6
  Top Side w0.127: v2(120.118,30.199) 120.118,31.525 122.642,34.05 U1.F10@124.62,34.05
  Mid-Layer 1 w0.127: v2(104.938,26.146) 105.423,26.631 v2(105.423,28.381)
  Mid-Layer 2 w0.1: v4@120.116,30.201 v2(120.118,30.199)
  Mid-Layer 2 w0.127: v2(105.423,28.381) 106.389,27.415 117.334,27.415 v2(120.118,30.199)
  other v4: 105.423,28.381 120.118,30.199
P2.04_A: P4.7 P17.25 U16.9 | length 65.7
  Top Side w0.1: v1(105.284,29.061) 105.449,28.895 U16.9@105.998,28.895
  Mid-Layer 2 w0.1: v2(82.1,10.16) 105.378,10.16 v6(105.38,10.163)
  Mid-Layer 5 w0.1: v1(105.284,29.061) 105.38,28.964 v6(105.38,10.163)
  Mid-Layer 6 w0.1: v1(97.975,47.67) 98.302,47.342 98.475,47.342 102.462,43.356 102.462,32.385 104.387,30.46 105.488,30.46 105.713,30.235 105.713,29.49 v1(105.284,29.061)
  other v3: 105.38,10.163
  other v4: 82.1,10.16
  other v5: 105.38,10.163
P2.04_B: U4.2 U16.8 | length 4.4
  Top Side w0.152: U4.2@102.774,28.853 103.142,28.853 104.631,27.364 105.425,27.364 105.823,27.763 U16.8@105.823,28.32
P2.05: TP33.1 U1.G9 U16.10 | length 28
  Mid-Layer 1 w0.1: v4(106.543,33.8) 106.544,29.728 v2(106.111,29.295) 106.111,27.101 v2(107.067,26.146) ; v4(121.494,35.687) 122.561,35.687 123.848,34.4 v8(124.97,34.4)
  Mid-Layer 2 w0.1: v4(106.543,33.8) 115.935,33.8 117.822,35.687 v4(121.494,35.687)
P2.05_A: P4.8 P17.26 U16.12 | length 66.1
  Top Side w0.1: P17.26@82.1,15.24 v2(82.1,15.242) ; v1(105.346,30.095) U16.12@105.998,30.095
  Mid-Layer 2 w0.1: v2(82.1,15.242) 105.659,15.242 v5@105.661,15.243
  Mid-Layer 5 w0.1: v1(105.346,30.095) 105.686,29.755 v5(105.686,15.243)
  Mid-Layer 6 w0.1: v1(98,52.9) 97.602,52.502 97.602,47.517 98.725,46.393 99.133,46.393 102.252,43.274 102.252,32.302 104.459,30.095 v1(105.346,30.095)
  other v3: 105.686,15.243
  other v4: 82.1,15.242
  other v6: 105.686,15.243
P2.05_B: U4.1 U16.11 | length 6.8
  Top Side w0.152: U4.1@102.774,27.583 103.128,27.583 103.609,27.101 105.544,27.101 106.855,28.413 106.855,29.458 106.618,29.695 U16.11@105.998,29.695
P2.06: P4.9 P12.12 U1.B9 | length 59
  Top Side w0.1: v1(124.057,59.228) P12.12@124.057,60.676
  Mid-Layer 1 w0.1: v4(119.179,32.394) 119.61,32.825 124.792,32.825 124.967,32.65 v8(124.97,32.65)
  Mid-Layer 2 w0.1: v1(100.515,47.67) 104.946,52.1 v1(121.3,52.1) 124.057,54.857 v1(124.057,59.228)
  Mid-Layer 5 w0.1: v4(119.179,32.394) 119.179,49.845 121.3,51.966 v1(121.3,52.1)
  other v3: 119.179,32.394
  other v5: 119.179,32.394
  other v6: 119.179,32.394
P2.07: P4.10 P11.6 P12.6 P12.14 U1.C9 | length 61.9
  Top Side w0.1: v1(120.247,59.228) P12.6@120.247,60.676 ; v1(125.327,59.228) P12.14@125.327,60.676
  Mid-Layer 1 w0.1: v3(117.093,32.744) 117.376,33.027 124.94,33.027 124.967,33 v8(124.97,33)
  Mid-Layer 3 w0.1: v1(100.515,52.75) 102.566,54.8 v1(117.4,54.8) 120.247,57.647 v1(120.247,59.228) 120.666,59.647 124.908,59.647 v1(125.327,59.228)
  Mid-Layer 5 w0.1: v3(117.093,32.744) 117.093,54.494 v1(117.4,54.8)
  other v4: 117.093,32.744
  other v5: 117.093,32.744
  other v6: 117.093,32.744
P2.08: P4.11 P12.16 U1.D9 | length 63
  Top Side w0.1: P4.11@103.055,47.67 cw(c103.055,47.725) 103,47.725 103,49.856 103.645,50.5 116.955,50.5 118.387,51.932 v1(118.387,54.35) ; v1(126.597,59.228) P12.16@126.597,60.676
  Mid-Layer 1 w0.1: v3(117.473,33.355) 117.622,33.505 124.812,33.505 124.967,33.35 v8(124.97,33.35)
  Mid-Layer 3 w0.1: v1(118.387,54.35) 124.176,54.35 126.597,56.771 v1(126.597,59.228)
  Mid-Layer 5 w0.1: v3(117.473,33.355) 117.473,53.436 v1(118.387,54.35)
  other v4: 117.473,33.355
  other v5: 117.473,33.355
  other v6: 117.473,33.355
P2.09: P4.12 P12.18 U1.E9 | length 57.1
  Top Side w0.1: v1(127.867,59.228) P12.18@127.867,60.676
  Mid-Layer 1 w0.1: v3(118.008,33.846) 118.135,33.718 124.922,33.718 cw(c124.922,33.667) v8@124.964,33.696
  Mid-Layer 3 w0.1: v1(103.055,52.75) 104.106,53.8 v1(118.8,53.8) 119.13,54.13 124.255,54.13 126.824,56.699 126.824,58.186 v1(127.867,59.228)
  Mid-Layer 5 w0.1: v3(118.008,33.846) 118,33.854 118,53 v1(118.8,53.8)
  other v4: 118.008,33.846
  other v5: 118.008,33.846
  other v6: 118.008,33.846
  other v8: 124.97,33.7
P2.10: P4.13 P12.20 U1.F9 | length 59.1
  Top Side w0.1: P4.13@105.595,47.67 105.595,48.598 107.097,50.1 122.963,50.1 ccw(c122.963,50.19) 123.026,50.127 v1(123.8,50.9) ; v1(129.137,59.228) P12.20@129.137,60.676
  Mid-Layer 1 w0.1: v6(119.623,34.161) 121.741,34.161 121.855,34.047 v8@124.965,34.047
  Mid-Layer 3 w0.1: v1(123.8,50.9) 126.97,50.9 129.137,53.067 v1(129.137,59.228)
  Mid-Layer 5 w0.1: v6(119.623,34.161) 119.623,48.901 121.623,50.9 v1(123.8,50.9)
  other v3: 119.623,34.161
  other v4: 119.623,34.161
  other v5: 119.623,34.161
  other v8: 124.97,34.05
P3.00: P5.3 P17.9 U1.H7 | length 90.5
  Top Side w0.1: P17.9@61.78,10.16 v2(61.78,10.169)
  Mid-Layer 2 w0.1: v2(61.78,10.169) 62.768,11.156 v6(92.699,11.156)
  Mid-Layer 3 w0.1: v3(124.034,34.945) 124.507,34.945 124.701,34.75 v8(125.67,34.75)
  Mid-Layer 4 w0.1: v6(92.895,36.645) 93.584,35.956 122.738,35.956 123.75,34.945 v3(124.034,34.945)
  Mid-Layer 5 w0.1: v6(92.699,11.156) 92.701,11.158 92.701,32.082 92.895,32.277 v6(92.895,36.645)
  other v2: 92.895,36.645
  other v3: 92.699,11.156 92.895,36.645
  other v4: 61.78,10.169 92.895,36.645
  other v5: 92.699,11.156 92.895,36.645
  other v9: 125.67,34.75
  other v11: 125.67,34.75
P3.01: P5.4 P17.10 U1.H6 | length 94.9
  Top Side w0.1: v2(61.775,15.24) P17.10@61.78,15.24
  Mid-Layer 2 w0.1: v2(61.775,15.24) 63.315,13.7 v5(93.05,13.701) ; v2(92.895,40.64) 93.21,40.955 117.843,40.955 123.736,35.061 125.757,35.061 126.02,34.797 v9(126.02,34.75)
  Mid-Layer 5 w0.1: v2(92.895,40.64) 93.214,40.321 93.214,32.041 93.05,31.876 v5(93.05,13.701)
  other v3: 93.05,13.701 92.895,40.64
  other v4: 61.775,15.24 92.895,40.64
  other v5: 92.895,40.64
  other v6: 93.05,13.701 92.895,40.64
  other v8: 126.02,34.75
P3.02: P5.5 P17.13 U1.H5 | length 103.8
  Mid-Layer 2 w0.1: v2(66.86,10.16) 67.42,10.72 v6(95.193,10.72) ; v5(94.573,43.698) 126.606,43.698 127.482,42.822 127.482,39.085 127.195,38.798 127.195,35.58 126.37,34.756 v8(126.37,34.75)
  Mid-Layer 5 w0.1: v5(94.573,43.698) 94.573,38.145 95.435,37.284 v6(95.435,35.56) 95.435,25.73 95.194,25.489 v6(95.193,10.72) v6(95.193,10.72)
  other v2: 95.435,35.56
  other v3: 95.193,10.72 95.435,35.56 94.573,43.698
  other v4: 66.86,10.16 95.435,35.56
  other v5: 95.193,10.72 95.435,35.56
  other v6: 94.573,43.698
  other v9: 126.37,34.75
P3.03: P5.6 P17.14 U1.H4 | length 102.6
  Top Side w0.1: P17.14@66.86,15.24 v2(66.864,15.24)
  Mid-Layer 2 w0.1: v2(66.864,15.24) 67.874,14.23 v5@95.421,14.23 ; v5(95.435,44.819) 95.929,45.313 125.985,45.313 128.149,43.149 128.149,38.03 127.478,37.359 127.478,35.525 126.72,34.767 v8(126.72,34.75)
  Mid-Layer 5 w0.1: v5(95.435,44.819) v6(95.435,40.64) 95.435,38.492 95.739,38.188 95.739,25.666 95.524,25.45 v5(95.524,14.23)
  other v2: 95.435,40.64
  other v3: 95.524,14.23 95.435,40.64 95.435,44.819
  other v4: 66.864,15.24 95.435,40.64
  other v5: 95.435,40.64
  other v6: 95.524,14.23 95.435,44.819
  other v9: 126.72,34.75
